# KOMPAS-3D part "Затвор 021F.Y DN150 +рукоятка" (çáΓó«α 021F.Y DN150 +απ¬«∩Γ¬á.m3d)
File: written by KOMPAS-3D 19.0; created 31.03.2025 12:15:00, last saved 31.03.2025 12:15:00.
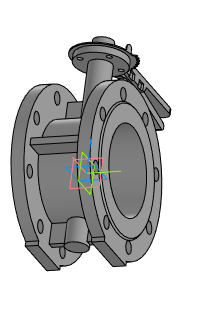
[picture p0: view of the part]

Document properties: Автор: Евгений; Полное имя файла: Затвор 021F.Y DN150 +рукоятка.a3d

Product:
- Part/product: Затвор 021F.Y DN150 +рукоятка
    Масса: 33.1008

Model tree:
1. Операция без истории:1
